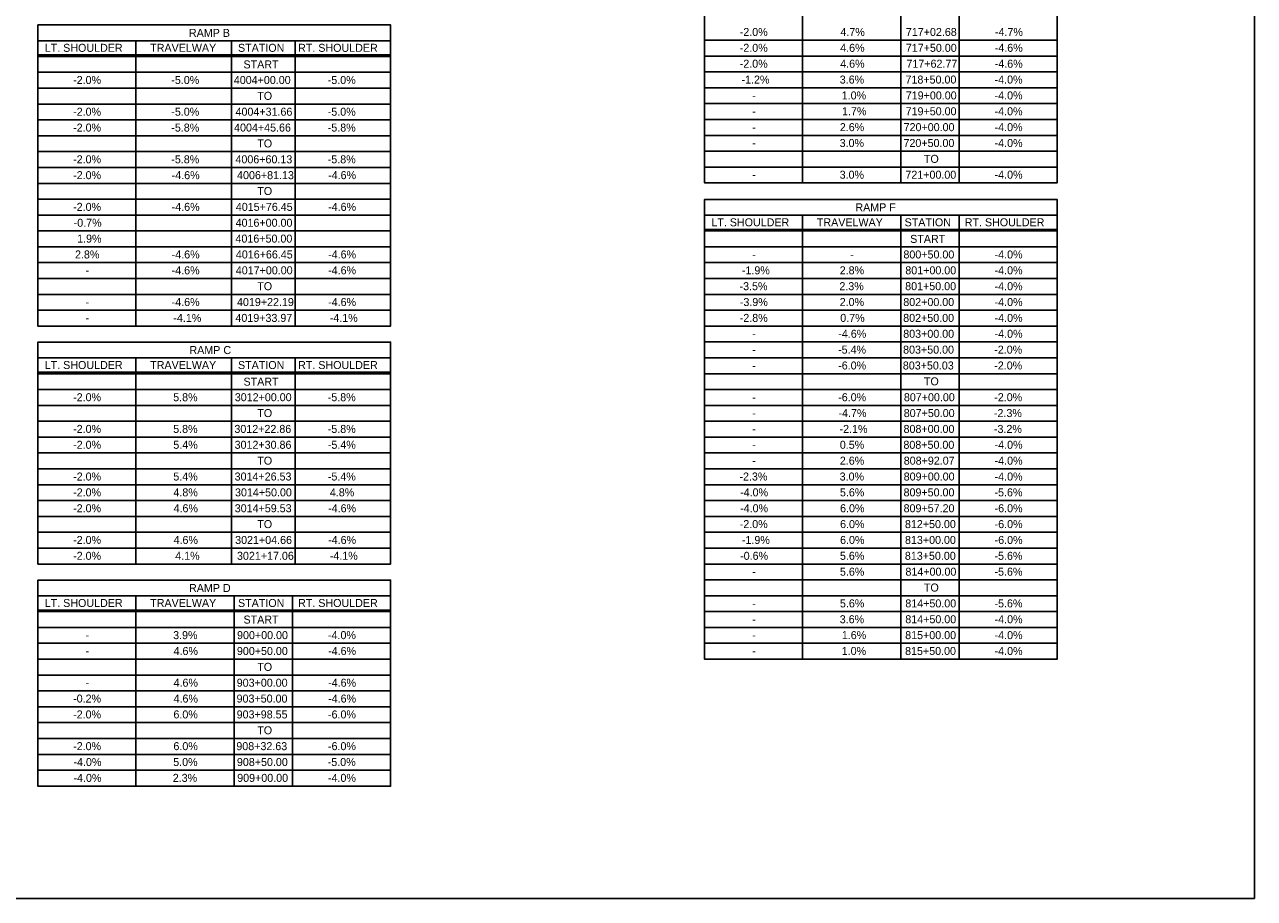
# Model space of a CAD drawing. Extents: x -15319374 to 1762012, y 465773 to 3693661.
# Drawn here: x -15314043.3 to -15313582.2, y 3693071.2 to 3693398.6 of the extents above; entities that cross this region are included whole.
import ezdxf

# ---------------------------------------------------------------- set-up
doc = ezdxf.new("R2010")
doc.units = 0
for name, color, linetype in [('BORDER', 7, 'Continuous'), ('Default', 7, 'Continuous'), ('DIMENSIONS', 7, 'Continuous')]:
    doc.layers.add(name, color=color, linetype=linetype)

msp = doc.modelspace()

# ---------------------------------------------------------------- linework, layer by layer
at = {"layer": 'BORDER'}
for p, q in [((-15313788.34, 3693493.72), (-15313788.34, 3693375.52)), ((-15313751.57, 3693493.72), (-15313751.57, 3693339.28)), ((-15313714.8, 3693493.72), (-15313714.8, 3693339.28)), ((-15313692.92, 3693493.72), (-15313692.92, 3693339.28)), ((-15314038.26, 3693392.53), (-15314038.26, 3693285.63)), ((-15314001.5, 3693392.53), (-15314001.5, 3693285.63)), ((-15313965.73, 3693392.53), (-15313965.73, 3693285.63)), ((-15313941.85, 3693392.53), (-15313941.85, 3693285.63)), ((-15313906.08, 3693392.53), (-15313906.08, 3693285.63)), ((-15313788.34, 3693392.76), (-15313656.16, 3693392.76)), ((-15314038.26, 3693387.25), (-15313906.08, 3693387.25)), ((-15314038.26, 3693386.65), (-15313906.08, 3693386.65)), ((-15313788.34, 3693386.82), (-15313656.16, 3693386.82)), ((-15314038.26, 3693380.71), (-15313906.08, 3693380.71)), ((-15314038.26, 3693380.71), (-15313906.08, 3693380.71)), ((-15314038.26, 3693380.71), (-15313906.08, 3693380.71)), ((-15313788.34, 3693380.87), (-15313656.16, 3693380.87)), ((-15314038.26, 3693374.77), (-15313906.08, 3693374.77)), ((-15313788.34, 3693374.93), (-15313656.16, 3693374.93)), ((-15314038.26, 3693368.83), (-15313906.08, 3693368.83)), ((-15313788.34, 3693368.99), (-15313656.16, 3693368.99)), ((-15314038.26, 3693362.88), (-15313906.08, 3693362.88)), ((-15313788.34, 3693363.05), (-15313656.16, 3693363.05)), ((-15314038.26, 3693356.94), (-15313906.08, 3693356.94)), ((-15313788.34, 3693357.1), (-15313656.16, 3693357.1)), ((-15314038.26, 3693351), (-15313906.08, 3693351)), ((-15313788.34, 3693351.16), (-15313656.16, 3693351.16)), ((-15314038.26, 3693345.06), (-15313906.08, 3693345.06)), ((-15313788.34, 3693345.22), (-15313656.16, 3693345.22)), ((-15314038.26, 3693339.11), (-15313906.08, 3693339.11)), ((-15314038.26, 3693333.17), (-15313906.08, 3693333.17)), ((-15314038.26, 3693327.23), (-15313906.08, 3693327.23)), ((-15313788.34, 3693327.16), (-15313788.34, 3693208.96)), ((-15313751.57, 3693327.16), (-15313751.57, 3693160.83)), ((-15313714.8, 3693327.16), (-15313714.8, 3693160.83)), ((-15313692.92, 3693327.16), (-15313692.92, 3693160.83)), ((-15314038.26, 3693321.28), (-15313906.08, 3693321.28)), ((-15313788.34, 3693321.88), (-15313656.16, 3693321.88)), ((-15313788.34, 3693321.28), (-15313656.16, 3693321.28)), ((-15314038.26, 3693315.34), (-15313906.08, 3693315.34)), ((-15313788.34, 3693315.34), (-15313656.16, 3693315.34)), ((-15313788.34, 3693315.34), (-15313656.16, 3693315.34)), ((-15313788.34, 3693315.34), (-15313656.16, 3693315.34)), ((-15314038.26, 3693309.4), (-15313906.08, 3693309.4)), ((-15313788.34, 3693309.4), (-15313656.16, 3693309.4)), ((-15314038.26, 3693303.46), (-15313906.08, 3693303.46)), ((-15313788.34, 3693303.46), (-15313656.16, 3693303.46)), ((-15314038.26, 3693297.51), (-15313906.08, 3693297.51)), ((-15313788.34, 3693297.51), (-15313656.16, 3693297.51)), ((-15314038.26, 3693291.57), (-15313906.08, 3693291.57)), ((-15313788.34, 3693291.57), (-15313656.16, 3693291.57)), ((-15313788.34, 3693285.63), (-15313656.16, 3693285.63)), ((-15313788.34, 3693279.69), (-15313656.16, 3693279.69)), ((-15314038.26, 3693273.68), (-15314038.26, 3693196.49)), ((-15314001.5, 3693273.68), (-15314001.5, 3693196.49)), ((-15313965.73, 3693273.68), (-15313965.73, 3693196.49)), ((-15313941.85, 3693273.68), (-15313941.85, 3693196.49)), ((-15313906.08, 3693273.68), (-15313906.08, 3693196.49)), ((-15313788.34, 3693273.74), (-15313656.16, 3693273.74)), ((-15314038.26, 3693268.4), (-15313906.08, 3693268.4)), ((-15314038.26, 3693267.8), (-15313906.08, 3693267.8)), ((-15313788.34, 3693267.8), (-15313656.16, 3693267.8)), ((-15314038.26, 3693261.86), (-15313906.08, 3693261.86)), ((-15314038.26, 3693261.86), (-15313906.08, 3693261.86)), ((-15314038.26, 3693261.86), (-15313906.08, 3693261.86)), ((-15313788.34, 3693261.86), (-15313656.16, 3693261.86)), ((-15314038.26, 3693255.91), (-15313906.08, 3693255.91)), ((-15313788.34, 3693255.91), (-15313656.16, 3693255.91)), ((-15314038.26, 3693249.97), (-15313906.08, 3693249.97)), ((-15313788.34, 3693249.97), (-15313656.16, 3693249.97)), ((-15314038.26, 3693244.03), (-15313906.08, 3693244.03)), ((-15313788.34, 3693244.03), (-15313656.16, 3693244.03)), ((-15314038.26, 3693238.09), (-15313906.08, 3693238.09)), ((-15313788.34, 3693238.09), (-15313656.16, 3693238.09)), ((-15314038.26, 3693232.14), (-15313906.08, 3693232.14)), ((-15313788.34, 3693232.14), (-15313656.16, 3693232.14)), ((-15314038.26, 3693226.2), (-15313906.08, 3693226.2)), ((-15313788.34, 3693226.2), (-15313656.16, 3693226.2)), ((-15314038.26, 3693220.26), (-15313906.08, 3693220.26)), ((-15313788.34, 3693220.26), (-15313656.16, 3693220.26)), ((-15314038.26, 3693214.32), (-15313906.08, 3693214.32)), ((-15313788.34, 3693214.32), (-15313656.16, 3693214.32)), ((-15314038.26, 3693208.37), (-15313906.08, 3693208.37)), ((-15313788.34, 3693208.37), (-15313656.16, 3693208.37)), ((-15314038.26, 3693202.43), (-15313906.08, 3693202.43)), ((-15313788.34, 3693202.43), (-15313656.16, 3693202.43)), ((-15313788.34, 3693196.49), (-15313656.16, 3693196.49)), ((-15313788.34, 3693190.54), (-15313656.16, 3693190.54)), ((-15314038.26, 3693184.53), (-15314038.26, 3693113.22)), ((-15314001.5, 3693184.53), (-15314001.5, 3693113.22)), ((-15313964.73, 3693184.53), (-15313964.73, 3693113.22)), ((-15313942.85, 3693184.53), (-15313942.85, 3693113.22)), ((-15313788.34, 3693184.6), (-15313656.16, 3693184.6)), ((-15314038.26, 3693179.25), (-15313906.08, 3693179.25)), ((-15314038.26, 3693178.66), (-15313906.08, 3693178.66)), ((-15313788.34, 3693178.66), (-15313656.16, 3693178.66)), ((-15314038.26, 3693172.71), (-15313906.08, 3693172.71)), ((-15314038.26, 3693172.71), (-15313906.08, 3693172.71)), ((-15314038.26, 3693172.71), (-15313906.08, 3693172.71)), ((-15313788.34, 3693172.72), (-15313656.16, 3693172.72)), ((-15314038.26, 3693166.77), (-15313906.08, 3693166.77)), ((-15313788.34, 3693166.77), (-15313656.16, 3693166.77)), ((-15314038.26, 3693160.83), (-15313906.08, 3693160.83)), ((-15314038.26, 3693154.89), (-15313906.08, 3693154.89)), ((-15314038.26, 3693148.94), (-15313906.08, 3693148.94)), ((-15314038.26, 3693143), (-15313906.08, 3693143)), ((-15314038.26, 3693137.06), (-15313906.08, 3693137.06)), ((-15314038.26, 3693131.11), (-15313906.08, 3693131.11)), ((-15314038.26, 3693125.17), (-15313906.08, 3693125.17)), ((-15314038.26, 3693119.23), (-15313906.08, 3693119.23)), ((-15314038.26, 3693113.29), (-15313906.08, 3693113.29))]:
    msp.add_line(p, q, dxfattribs=at)
for points in [[(-15313788.34, 3693493.72), (-15313656.16, 3693493.72), (-15313656.16, 3693339.28), (-15313788.34, 3693339.28)], [(-15314038.26, 3693392.53), (-15313906.08, 3693392.53), (-15313906.08, 3693285.63), (-15314038.26, 3693285.63)], [(-15313788.34, 3693327.16), (-15313656.16, 3693327.16), (-15313656.16, 3693160.83), (-15313788.34, 3693160.83)], [(-15314038.26, 3693273.68), (-15313906.08, 3693273.68), (-15313906.08, 3693196.49), (-15314038.26, 3693196.49)], [(-15314038.26, 3693184.53), (-15313906.08, 3693184.53), (-15313906.08, 3693113.22), (-15314038.26, 3693113.22)]]:
    msp.add_lwpolyline(points, close=True, dxfattribs=at)
for points in [[(-15314038.26, 3693392.53), (-15314038.26, 3693398.47), (-15313906.08, 3693398.47), (-15313906.08, 3693392.53)], [(-15313788.34, 3693327.16), (-15313788.34, 3693333.1), (-15313656.16, 3693333.1), (-15313656.16, 3693327.16)], [(-15314038.26, 3693273.68), (-15314038.26, 3693279.62), (-15313906.08, 3693279.62), (-15313906.08, 3693273.68)], [(-15314038.26, 3693184.53), (-15314038.26, 3693190.48), (-15313906.08, 3693190.48), (-15313906.08, 3693184.53)]]:
    msp.add_lwpolyline(points, dxfattribs=at)
at = {"layer": 'Default'}
msp.add_lwpolyline([(-15314452.76, 3693660.68), (-15313582.2, 3693660.68), (-15313582.2, 3693071.2), (-15314452.76, 3693071.2)], close=True, dxfattribs=at)

# ---------------------------------------------------------------- texts
at = {"layer": 'DIMENSIONS'}
for s, p in [('RAMP B', (-15313981.65, 3693394)), ('-2.0%', (-15313775.15, 3693394.33)), ('4.7%', (-15313737.41, 3693394.33)), ('717+02.68', (-15313712.87, 3693394.33)), ('-4.7%', (-15313679.47, 3693394.33)), ('LT. SHOULDER', (-15314035.71, 3693388.39)), ('TRAVELWAY', (-15313996.17, 3693388.39)), ('STATION', (-15313963.26, 3693388.39)), ('RT. SHOULDER', (-15313940.73, 3693388.39)), ('-2.0%', (-15313775.15, 3693388.39)), ('4.6%', (-15313737.48, 3693388.39)), ('717+50.00', (-15313712.88, 3693388.39)), ('-4.6%', (-15313679.55, 3693388.39)), ('START', (-15313961.19, 3693382.17)), ('-2.0%', (-15313775.15, 3693382.44)), ('4.6%', (-15313737.48, 3693382.44)), ('717+62.77', (-15313712.65, 3693382.44)), ('-4.6%', (-15313679.55, 3693382.44)), ('-2.0%', (-15314025.07, 3693376.34)), ('-5.0%', (-15313988.26, 3693376.34)), ('4004+00.00', (-15313964.82, 3693376.34)), ('-5.0%', (-15313929.61, 3693376.34)), ('-1.2%', (-15313774.48, 3693376.5)), ('3.6%', (-15313737.65, 3693376.5)), ('718+50.00', (-15313713, 3693376.5)), ('-4.0%', (-15313679.59, 3693376.5)), ('TO', (-15313956.03, 3693370.4)), ('-', (-15313770.46, 3693370.56)), ('1.0%', (-15313736.91, 3693370.56)), ('719+00.00', (-15313712.9, 3693370.56)), ('-4.0%', (-15313679.59, 3693370.56)), ('-2.0%', (-15314025.07, 3693364.45)), ('-5.0%', (-15313988.26, 3693364.45)), ('4004+31.66', (-15313964.18, 3693364.45)), ('-5.0%', (-15313929.61, 3693364.45)), ('-', (-15313770.46, 3693364.62)), ('1.7%', (-15313736.8, 3693364.62)), ('719+50.00', (-15313712.95, 3693364.62)), ('-4.0%', (-15313679.59, 3693364.62)), ('-2.0%', (-15314025.07, 3693358.51)), ('-5.8%', (-15313988.26, 3693358.51)), ('4004+45.66', (-15313964.72, 3693358.51)), ('-5.8%', (-15313929.61, 3693358.51)), ('2.6%', (-15313737.62, 3693358.67)), ('720+00.00', (-15313713.71, 3693358.67)), ('-4.0%', (-15313679.59, 3693358.67)), ('-', (-15313770.46, 3693358.67)), ('TO', (-15313956.03, 3693352.57)), ('-', (-15313770.46, 3693352.73)), ('3.0%', (-15313737.69, 3693352.73)), ('720+50.00', (-15313713.76, 3693352.73)), ('-4.0%', (-15313679.59, 3693352.73)), ('-2.0%', (-15314025.07, 3693346.62)), ('-5.8%', (-15313988.26, 3693346.62)), ('4006+60.13', (-15313964.21, 3693346.62)), ('-5.8%', (-15313929.61, 3693346.62)), ('TO', (-15313706.1, 3693346.79)), ('-2.0%', (-15314025.07, 3693340.68)), ('-4.6%', (-15313988.12, 3693340.68)), ('4006+81.13', (-15313963.6, 3693340.68)), ('-4.6%', (-15313929.47, 3693340.68)), ('3.0%', (-15313737.69, 3693340.85)), ('721+00.00', (-15313713.05, 3693340.85)), ('-4.0%', (-15313679.59, 3693340.85)), ('-', (-15313770.46, 3693340.85)), ('TO', (-15313956.03, 3693334.74)), ('-2.0%', (-15314025.07, 3693328.8)), ('-4.6%', (-15313988.12, 3693328.8)), ('4015+76.45', (-15313964.07, 3693328.8)), ('-4.6%', (-15313929.47, 3693328.8)), ('RAMP F', (-15313731.79, 3693328.63)), ('-0.7%', (-15314024.86, 3693322.85)), ('4016+00.00', (-15313964.15, 3693322.85)), ('LT. SHOULDER', (-15313785.78, 3693323.02)), ('TRAVELWAY', (-15313746.24, 3693323.02)), ('STATION', (-15313713.34, 3693323.02)), ('RT. SHOULDER', (-15313690.8, 3693323.02)), ('1.9%', (-15314023.56, 3693316.91)), ('4016+50.00', (-15313964.2, 3693316.91)), ('START', (-15313711.26, 3693316.8)), ('2.8%', (-15314024.36, 3693310.97)), ('-4.6%', (-15313988.12, 3693310.97)), ('4016+66.45', (-15313964.05, 3693310.97)), ('-4.6%', (-15313929.47, 3693310.97)), ('-', (-15313770.46, 3693310.97)), ('-', (-15313733.69, 3693310.97)), ('800+50.00', (-15313713.78, 3693310.97)), ('-4.0%', (-15313679.59, 3693310.97)), ('-', (-15314020.39, 3693305.03)), ('-4.6%', (-15313988.12, 3693305.03)), ('4017+00.00', (-15313964.08, 3693305.03)), ('-4.6%', (-15313929.47, 3693305.03)), ('-1.9%', (-15313774.34, 3693305.03)), ('2.8%', (-15313737.67, 3693305.03)), ('801+00.00', (-15313713.07, 3693305.03)), ('-4.0%', (-15313679.59, 3693305.03)), ('TO', (-15313956.03, 3693299.08)), ('-3.5%', (-15313775.22, 3693299.08)), ('2.3%', (-15313737.79, 3693299.08)), ('801+50.00', (-15313713.12, 3693299.08)), ('-4.0%', (-15313679.59, 3693299.08)), ('-', (-15314020.39, 3693293.14)), ('-4.6%', (-15313988.12, 3693293.14)), ('4019+22.19', (-15313963.63, 3693293.14)), ('-4.6%', (-15313929.47, 3693293.14)), ('-3.9%', (-15313775.12, 3693293.14)), ('2.0%', (-15313737.67, 3693293.14)), ('802+00.00', (-15313713.83, 3693293.14)), ('-4.0%', (-15313679.59, 3693293.14)), ('-', (-15314020.39, 3693287.2)), ('-4.1%', (-15313987.5, 3693287.2)), ('4019+33.97', (-15313964.22, 3693287.2)), ('-4.1%', (-15313928.86, 3693287.2)), ('-2.8%', (-15313775.15, 3693287.2)), ('0.7%', (-15313737.46, 3693287.2)), ('802+50.00', (-15313713.87, 3693287.2)), ('-4.0%', (-15313679.59, 3693287.2)), ('-4.6%', (-15313738.19, 3693281.25)), ('803+00.00', (-15313713.85, 3693281.25)), ('-4.0%', (-15313679.59, 3693281.25)), ('-', (-15313770.46, 3693281.25)), ('-5.4%', (-15313738.28, 3693275.31)), ('803+50.00', (-15313713.9, 3693275.31)), ('-2.0%', (-15313679.73, 3693275.31)), ('RAMP C', (-15313981.45, 3693275.15)), ('-', (-15313770.46, 3693275.31)), ('LT. SHOULDER', (-15314035.71, 3693269.54)), ('TRAVELWAY', (-15313996.17, 3693269.54)), ('STATION', (-15313963.26, 3693269.54)), ('RT. SHOULDER', (-15313940.73, 3693269.54)), ('-', (-15313770.46, 3693269.37)), ('-6.0%', (-15313738.24, 3693269.37)), ('803+50.03', (-15313714, 3693269.37)), ('-2.0%', (-15313679.73, 3693269.37)), ('START', (-15313961.19, 3693263.31)), ('TO', (-15313706.1, 3693263.43)), ('-2.0%', (-15314025.07, 3693257.48)), ('5.8%', (-15313987.55, 3693257.48)), ('3012+00.00', (-15313964.46, 3693257.48)), ('-5.8%', (-15313929.61, 3693257.48)), ('-6.0%', (-15313738.24, 3693257.48)), ('807+00.00', (-15313713.61, 3693257.48)), ('-2.0%', (-15313679.73, 3693257.48)), ('-', (-15313770.46, 3693257.48)), ('TO', (-15313956.03, 3693251.54)), ('-', (-15313770.46, 3693251.54)), ('-4.7%', (-15313738.12, 3693251.54)), ('807+50.00', (-15313713.66, 3693251.54)), ('-2.3%', (-15313679.85, 3693251.54)), ('-2.0%', (-15314025.07, 3693245.6)), ('5.8%', (-15313987.55, 3693245.6)), ('3012+22.86', (-15313964.6, 3693245.6)), ('-5.8%', (-15313929.61, 3693245.6)), ('-', (-15313770.46, 3693245.6)), ('-2.1%', (-15313737.72, 3693245.6)), ('808+00.00', (-15313713.73, 3693245.6)), ('-3.2%', (-15313679.85, 3693245.6)), ('-2.0%', (-15314025.07, 3693239.66)), ('5.4%', (-15313987.5, 3693239.66)), ('3012+30.86', (-15313964.53, 3693239.66)), ('-5.4%', (-15313929.57, 3693239.66)), ('0.5%', (-15313737.62, 3693239.66)), ('808+50.00', (-15313713.78, 3693239.66)), ('-4.0%', (-15313679.59, 3693239.66)), ('-', (-15313770.46, 3693239.66)), ('TO', (-15313956.03, 3693233.71)), ('-', (-15313770.46, 3693233.71)), ('2.6%', (-15313737.62, 3693233.71)), ('808+92.07', (-15313713.66, 3693233.71)), ('-4.0%', (-15313679.59, 3693233.71)), ('-2.0%', (-15314025.07, 3693227.77)), ('5.4%', (-15313987.5, 3693227.77)), ('3014+26.53', (-15313964.52, 3693227.77)), ('-5.4%', (-15313929.57, 3693227.77)), ('-2.3%', (-15313775.26, 3693227.77)), ('3.0%', (-15313737.69, 3693227.77)), ('809+00.00', (-15313713.68, 3693227.77)), ('-4.0%', (-15313679.59, 3693227.77)), ('-2.0%', (-15314025.07, 3693221.83)), ('4.8%', (-15313987.46, 3693221.83)), ('3014+50.00', (-15313964.37, 3693221.83)), ('4.8%', (-15313928.81, 3693221.83)), ('-4.0%', (-15313775, 3693221.83)), ('5.6%', (-15313737.58, 3693221.83)), ('809+50.00', (-15313713.73, 3693221.83)), ('-5.6%', (-15313679.64, 3693221.83)), ('-2.0%', (-15314025.07, 3693215.88)), ('4.6%', (-15313987.41, 3693215.88)), ('3014+59.53', (-15313964.47, 3693215.88)), ('-4.6%', (-15313929.47, 3693215.88)), ('-4.0%', (-15313775, 3693215.88)), ('6.0%', (-15313737.53, 3693215.88)), ('809+57.20', (-15313713.71, 3693215.88)), ('-6.0%', (-15313679.59, 3693215.88)), ('TO', (-15313956.03, 3693209.94)), ('-2.0%', (-15313775.15, 3693209.94)), ('6.0%', (-15313737.53, 3693209.94)), ('812+50.00', (-15313713.21, 3693209.94)), ('-6.0%', (-15313679.59, 3693209.94)), ('-2.0%', (-15314025.07, 3693204)), ('4.6%', (-15313987.41, 3693204)), ('3021+04.66', (-15313964.32, 3693204)), ('-4.6%', (-15313929.47, 3693204)), ('-1.9%', (-15313774.34, 3693204)), ('6.0%', (-15313737.53, 3693204)), ('813+00.00', (-15313713.19, 3693204)), ('-6.0%', (-15313679.59, 3693204)), ('-2.0%', (-15314025.07, 3693198.06)), ('4.1%', (-15313986.79, 3693198.06)), ('3021+17.06', (-15313963.63, 3693198.06)), ('-4.1%', (-15313928.86, 3693198.06)), ('-0.6%', (-15313775, 3693198.06)), ('5.6%', (-15313737.58, 3693198.06)), ('813+50.00', (-15313713.24, 3693198.06)), ('-5.6%', (-15313679.64, 3693198.06)), ('-', (-15313770.46, 3693192.11)), ('5.6%', (-15313737.58, 3693192.11)), ('814+00.00', (-15313713.02, 3693192.11)), ('-5.6%', (-15313679.64, 3693192.11)), ('RAMP D', (-15313981.61, 3693186)), ('TO', (-15313706.1, 3693186.17)), ('LT. SHOULDER', (-15314035.71, 3693180.39)), ('TRAVELWAY', (-15313996.17, 3693180.39)), ('STATION', (-15313963.26, 3693180.39)), ('RT. SHOULDER', (-15313940.73, 3693180.39)), ('-', (-15313770.46, 3693180.23)), ('5.6%', (-15313737.58, 3693180.23)), ('814+50.00', (-15313713.07, 3693180.23)), ('-5.6%', (-15313679.64, 3693180.23)), ('START', (-15313961.19, 3693174.17)), ('3.6%', (-15313737.65, 3693174.29)), ('814+50.00', (-15313713.07, 3693174.29)), ('-4.0%', (-15313679.59, 3693174.29)), ('-', (-15313770.46, 3693174.29)), ('-', (-15314020.39, 3693168.34)), ('3.9%', (-15313987.57, 3693168.34)), ('900+00.00', (-15313963.61, 3693168.34)), ('-4.0%', (-15313929.52, 3693168.34)), ('-', (-15313770.46, 3693168.34)), ('1.6%', (-15313736.87, 3693168.34)), ('815+00.00', (-15313713.12, 3693168.34)), ('-4.0%', (-15313679.59, 3693168.34)), ('-', (-15314020.39, 3693162.4)), ('4.6%', (-15313987.41, 3693162.4)), ('900+50.00', (-15313963.66, 3693162.4)), ('-4.6%', (-15313929.47, 3693162.4)), ('-', (-15313770.46, 3693162.4)), ('1.0%', (-15313736.91, 3693162.4)), ('815+50.00', (-15313713.16, 3693162.4)), ('-4.0%', (-15313679.59, 3693162.4)), ('TO', (-15313956.03, 3693156.45)), ('-', (-15314020.39, 3693150.51)), ('4.6%', (-15313987.41, 3693150.51)), ('903+00.00', (-15313963.73, 3693150.51)), ('-4.6%', (-15313929.47, 3693150.51)), ('-0.2%', (-15314025.07, 3693144.57)), ('4.6%', (-15313987.41, 3693144.57)), ('903+50.00', (-15313963.78, 3693144.57)), ('-4.6%', (-15313929.47, 3693144.57)), ('-2.0%', (-15314025.07, 3693138.63)), ('6.0%', (-15313987.46, 3693138.63)), ('903+98.55', (-15313963.76, 3693138.63)), ('-6.0%', (-15313929.52, 3693138.63)), ('TO', (-15313956.03, 3693132.68)), ('-2.0%', (-15314025.07, 3693126.74)), ('6.0%', (-15313987.46, 3693126.74)), ('908+32.63', (-15313963.88, 3693126.74)), ('-6.0%', (-15313929.52, 3693126.74)), ('-4.0%', (-15314024.93, 3693120.8)), ('5.0%', (-15313987.55, 3693120.8)), ('908+50.00', (-15313963.66, 3693120.8)), ('-5.0%', (-15313929.61, 3693120.8)), ('-4.0%', (-15314024.93, 3693114.86)), ('2.3%', (-15313987.71, 3693114.86)), ('909+00.00', (-15313963.56, 3693114.86)), ('-4.0%', (-15313929.52, 3693114.86))]:
    msp.add_text(s, height=3, dxfattribs=at).set_placement(p)

doc.saveas('drawing.dxf')
